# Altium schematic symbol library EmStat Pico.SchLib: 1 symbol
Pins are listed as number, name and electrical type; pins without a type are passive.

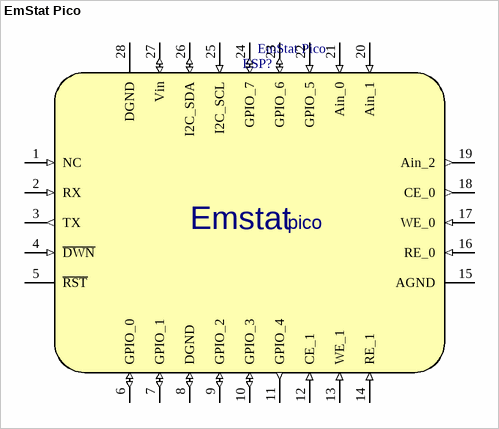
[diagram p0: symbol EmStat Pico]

## EmStat Pico
designator ESP?
footprint EmstatPico (EmStat Pico LandPattern)
pins: 1 NC (in), 2 RX (in), 3 TX (out), 4 ~{DWN} (in), 5 ~{RST} (power), 6 GPIO_0 (io), 7 GPIO_1 (io), 8 DGND (io), 9 GPIO_2 (io), 10 GPIO_3 (io), 11 GPIO_4 (out), 12 CE_1 (in), 13 WE_1 (in), 14 RE_1 (in), 15 AGND (power), 16 RE_0 (in), 17 WE_0 (in), 18 CE_0 (out), 19 Ain_2 (out), 20 Ain_1 (in), 21 Ain_0 (in), 22 GPIO_5 (in), 23 GPIO_6 (io), 24 GPIO_7 (io), 25 I2C_SCL (in), 26 I2C_SDA (io), 27 Vin (io), 28 DGND (power)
